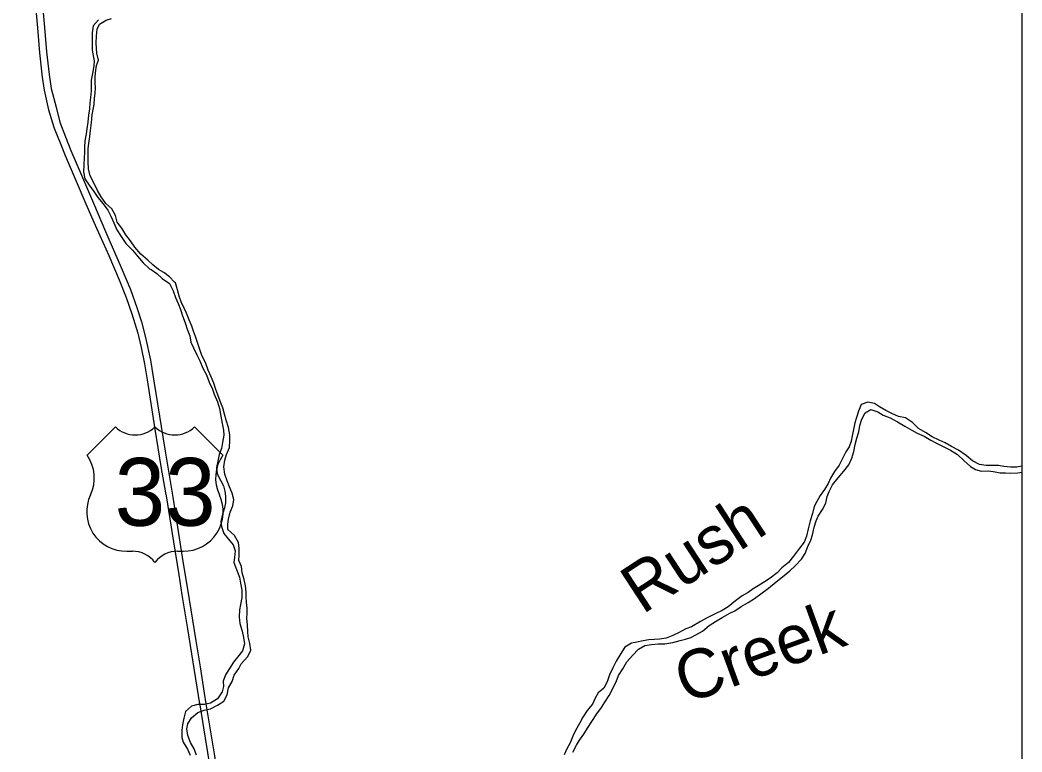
# Model space of a CAD drawing. Extents: x -51.9 to 34, y 0 to 23.3.
# Drawn here: x 9.235 to 12.658, y 13.737 to 16.239 of the extents above; entities that cross this region are included whole.
import ezdxf

# ---------------------------------------------------------------- set-up
doc = ezdxf.new("R2010")
doc.units = 0
for name, color, linetype in [('GM_X_Major_River', 7, 'Continuous'), ('GM_X_Major_River_Text', 7, 'Continuous'), ('GM_X_US_Route', 7, 'Continuous'), ('GM_X_US_Shield', 7, 'Continuous'), ('SH_Text', 7, 'Continuous')]:
    doc.layers.add(name, color=color, linetype=linetype)

msp = doc.modelspace()

# ---------------------------------------------------------------- linework, layer by layer
at = {"layer": 'GM_X_Major_River'}
for points in [[(9.5028, 16.2393), (9.4849, 16.2192), (9.4817, 16.1952), (9.4811, 16.1785), (9.4812, 16.1372), (9.4852, 16.1159), (9.4879, 16.0992), (9.4867, 16.0825), (9.4827, 16.0565), (9.4782, 16.0332), (9.4782, 16.0132), (9.4776, 15.9965), (9.4757, 15.9738), (9.4737, 15.9558), (9.4718, 15.9352), (9.4692, 15.9138), (9.4666, 15.8898), (9.4633, 15.8665), (9.4607, 15.8498), (9.4568, 15.8258), (9.4556, 15.8038), (9.4549, 15.7871), (9.4543, 15.7671), (9.4524, 15.7438), (9.4518, 15.7198), (9.4565, 15.6958), (9.4705, 15.6745), (9.4865, 15.6526), (9.5005, 15.6319), (9.5185, 15.6107), (9.5352, 15.5887), (9.5452, 15.5688), (9.5552, 15.5461), (9.5659, 15.5222), (9.58, 15.4989), (9.5966, 15.4756), (9.6186, 15.4523), (9.6359, 15.4317), (9.6559, 15.4091), (9.6772, 15.3885), (9.6832, 15.3866)], [(9.7657, 15.3402), (9.7624, 15.3428), (9.7457, 15.3614), (9.7258, 15.376), (9.7085, 15.3867), (9.6885, 15.4026), (9.6712, 15.4185), (9.6479, 15.4391), (9.6272, 15.4624), (9.6119, 15.4837), (9.5959, 15.5049), (9.5825, 15.5276), (9.5665, 15.5482), (9.5605, 15.5708), (9.5485, 15.5934), (9.5285, 15.612), (9.5118, 15.634), (9.4991, 15.6566), (9.4878, 15.6806), (9.4744, 15.7058), (9.4684, 15.7305), (9.4676, 15.7545), (9.4676, 15.7778), (9.4682, 15.7992), (9.4695, 15.8165), (9.4734, 15.8405), (9.476, 15.8612), (9.4786, 15.8885), (9.4811, 15.9152), (9.4844, 15.9332), (9.4877, 15.9499), (9.4896, 15.9719), (9.4916, 15.9892), (9.4922, 16.0066), (9.4915, 16.0252), (9.4914, 16.0459), (9.494, 16.0672), (9.4966, 16.0839), (9.5025, 16.1019), (9.4972, 16.1252), (9.4958, 16.1426), (9.4951, 16.1599), (9.4957, 16.1846), (9.4989, 16.2072), (9.5069, 16.2246), (9.5287, 16.2387), (9.5473, 16.2441)], [(9.6832, 15.3866), (9.7019, 15.3726), (9.7205, 15.3554), (9.7451, 15.3381), (9.7585, 15.3135), (9.7665, 15.2909), (9.7746, 15.2696), (9.7826, 15.2496), (9.79, 15.2276), (9.7993, 15.2036), (9.8054, 15.1823), (9.8154, 15.159), (9.8188, 15.1384), (9.8275, 15.1184), (9.8395, 15.0951), (9.8495, 15.0738), (9.8595, 15.0492), (9.8722, 15.0266), (9.8816, 15.0013), (9.8923, 14.9773), (9.8983, 14.9607), (9.909, 14.934), (9.9164, 14.9107), (9.9211, 14.8854), (9.9258, 14.8594), (9.9299, 14.8368), (9.9312, 14.8201), (9.9267, 14.7954), (9.9227, 14.7747), (9.9155, 14.7541), (9.9109, 14.7314), (9.9063, 14.71), (9.9084, 14.688), (9.9211, 14.6641), (9.9297, 14.6468), (9.9344, 14.6288), (9.9365, 14.6121), (9.9372, 14.5888)], [(9.9532, 14.5569), (9.9618, 14.5782), (9.9651, 14.6002), (9.9597, 14.6222), (9.951, 14.6435), (9.943, 14.6635), (9.9349, 14.6868), (9.9316, 14.7114), (9.9341, 14.7348), (9.9401, 14.7541), (9.9506, 14.7782), (9.9519, 14.8002), (9.9512, 14.8215), (9.9471, 14.8462), (9.9397, 14.8708), (9.933, 14.8914), (9.9277, 14.9134), (9.919, 14.9367), (9.9109, 14.958), (9.9042, 14.976), (9.8969, 14.9973), (9.8882, 15.0193), (9.8782, 15.0426), (9.8681, 15.0679), (9.8561, 15.0925), (9.8481, 15.1165), (9.8407, 15.1364), (9.834, 15.1578), (9.828, 15.1751), (9.8213, 15.1924), (9.8132, 15.2144), (9.8032, 15.237), (9.7952, 15.2543), (9.7858, 15.2756), (9.7798, 15.2922), (9.7724, 15.3162), (9.7657, 15.3402)], [(12.6582, 14.7138), (12.6404, 14.7104), (12.6192, 14.7103), (12.5959, 14.7129), (12.578, 14.7168), (12.5607, 14.7168), (12.5361, 14.7167), (12.5129, 14.7193), (12.4896, 14.7319), (12.4676, 14.7511), (12.4417, 14.7684), (12.4177, 14.781), (12.3964, 14.7942), (12.3751, 14.8028), (12.3519, 14.8141), (12.3286, 14.8293), (12.3053, 14.8433), (12.2846, 14.8632), (12.26, 14.8798), (12.2361, 14.8844), (12.2141, 14.8943), (12.1928, 14.9049), (12.1715, 14.9168), (12.1542, 14.9281), (12.1316, 14.9327), (12.1091, 14.9246), (12.0992, 14.9019), (12.0926, 14.8799), (12.0873, 14.8626), (12.0828, 14.8399), (12.0782, 14.8179), (12.0742, 14.7992), (12.0676, 14.7798), (12.0564, 14.7631), (12.0445, 14.7398), (12.0339, 14.7177), (12.0174, 14.6963), (12.0042, 14.673), (11.9956, 14.6549), (11.983, 14.6349), (11.9691, 14.6142), (11.9579, 14.5935), (11.9486, 14.5768), (11.9421, 14.5521), (11.9348, 14.5274), (11.9283, 14.5001), (11.9223, 14.4747), (11.9138, 14.454), (11.8946, 14.4293), (11.878, 14.4066), (11.8602, 14.3845), (11.8376, 14.3671), (11.8217, 14.349), (11.7979, 14.331), (11.7753, 14.3169), (11.7568, 14.3055)], [(11.8656, 14.3559), (11.8828, 14.3739), (11.9046, 14.396), (11.9179, 14.416), (11.9271, 14.4394), (11.9363, 14.4614), (11.9429, 14.4794), (11.9488, 14.5055), (11.9554, 14.5268), (11.962, 14.5435), (11.9766, 14.5655), (11.9885, 14.5882), (11.993, 14.6109), (11.999, 14.6276), (12.0109, 14.6503), (12.0301, 14.6744), (12.0499, 14.6971), (12.0665, 14.7192), (12.077, 14.7412), (12.0843, 14.7645), (12.0889, 14.7879), (12.0941, 14.8099), (12.1007, 14.8319), (12.104, 14.8533), (12.1106, 14.8746), (12.1225, 14.896), (12.1417, 14.9074), (12.1656, 14.9001), (12.1842, 14.8882), (12.2075, 14.8796), (12.2328, 14.8657), (12.2581, 14.8511), (12.2814, 14.8372), (12.3, 14.8273), (12.3239, 14.8167), (12.3466, 14.8027), (12.3639, 14.7935), (12.3885, 14.7809), (12.4138, 14.769), (12.4384, 14.7537), (12.4597, 14.7338), (12.4823, 14.7125), (12.4996, 14.7032), (12.5196, 14.6973), (12.5448, 14.6981), (12.5667, 14.6948), (12.584, 14.6909), (12.602, 14.6909), (12.6192, 14.6903), (12.6445, 14.6917), (12.6582, 14.6933)], [(9.9372, 14.5888), (9.9339, 14.5715), (9.9267, 14.5501), (9.9208, 14.5254), (9.9228, 14.5081), (9.9309, 14.4835), (9.9462, 14.4662), (9.9628, 14.4456), (9.9702, 14.4249), (9.9676, 14.4016), (9.965, 14.3849), (9.9744, 14.3609), (9.9844, 14.335), (9.9885, 14.3143), (9.9932, 14.2903), (9.9932, 14.265), (9.9887, 14.241), (9.9847, 14.223), (9.9835, 14.1997), (9.9862, 14.1763), (9.9936, 14.1504), (9.9983, 14.1284), (10.0017, 14.1071), (9.9951, 14.083), (9.9779, 14.061), (9.9646, 14.0443), (9.9507, 14.0222), (9.9369, 14.0008), (9.9289, 13.9795), (9.9297, 13.9608), (9.9251, 13.9428), (9.9092, 13.9188), (9.886, 13.9047), (9.8654, 13.8999), (9.8421, 13.8992), (9.8209, 13.8938), (9.7997, 13.8751), (9.7944, 13.8524), (9.7899, 13.8304), (9.7873, 13.8117), (9.7873, 13.787), (9.792, 13.7704), (9.8067, 13.7471), (9.8167, 13.7265)], [(9.838, 13.7265), (9.8299, 13.7478), (9.8173, 13.7698), (9.8086, 13.7938), (9.8052, 13.8164), (9.8078, 13.8331), (9.821, 13.8538), (9.8429, 13.8719), (9.8635, 13.8799), (9.886, 13.8847), (9.9092, 13.8974), (9.9311, 13.9108), (9.943, 13.9322), (9.9476, 13.9562), (9.9602, 13.9783), (9.9667, 14.0003), (9.982, 14.0223), (9.9906, 14.039), (10.0131, 14.0631), (10.0236, 14.0851), (10.0203, 14.1078), (10.0142, 14.1304), (10.0128, 14.1491), (10.0121, 14.1704), (10.01, 14.1944), (10.0107, 14.2111), (10.0106, 14.2284), (10.0086, 14.2497), (10.0072, 14.2671), (10.0071, 14.2837), (10.0051, 14.3051), (10.0004, 14.3264), (9.9937, 14.349), (9.9916, 14.371), (9.9829, 14.3916), (9.9835, 14.4096), (9.9841, 14.4323), (9.9814, 14.453), (9.9674, 14.4776), (9.9454, 14.4975), (9.9447, 14.5155), (9.9467, 14.5335), (9.9532, 14.5569)], [(11.1233, 13.7368), (11.1365, 13.7602), (11.1464, 13.7775), (11.161, 13.7982), (11.1742, 13.8183), (11.1881, 13.8417), (11.206, 13.8677), (11.2219, 13.8898), (11.2331, 13.9071), (11.2476, 13.9305), (11.2714, 13.9773), (11.28, 13.9986), (11.2946, 14.022), (11.3078, 14.0454), (11.3276, 14.0674), (11.3482, 14.0888), (11.3694, 14.1009), (11.392, 14.1043), (11.4152, 14.1064), (11.4378, 14.1071), (11.4657, 14.1112), (11.4909, 14.1186), (11.5088, 14.1227), (11.5267, 14.1288), (11.544, 14.1381), (11.5672, 14.1502), (11.5897, 14.1696), (11.6116, 14.183), (11.6335, 14.1964), (11.66, 14.2112), (11.6773, 14.2192), (11.6992, 14.234), (11.7224, 14.2481), (11.7443, 14.2621), (11.7655, 14.2782), (11.792, 14.297), (11.8185, 14.3184), (11.8404, 14.3364), (11.8656, 14.3559)], [(11.7568, 14.3055), (11.7395, 14.2948), (11.7223, 14.2821), (11.7017, 14.2713), (11.6798, 14.2533), (11.6547, 14.2338), (11.6341, 14.2211), (11.6096, 14.2097), (11.5804, 14.1943), (11.5598, 14.1829), (11.5286, 14.1654), (11.5101, 14.158), (11.4849, 14.144), (11.465, 14.1352), (11.4431, 14.1265), (11.4198, 14.1224), (11.4012, 14.1217), (11.3833, 14.121), (11.364, 14.1176), (11.3428, 14.1128), (11.3242, 14.1088), (11.3017, 14.0954), (11.2871, 14.074), (11.2712, 14.0473), (11.2607, 14.0246), (11.2494, 14.0005), (11.2409, 13.9765), (11.2296, 13.9551), (11.2098, 13.9391), (11.2005, 13.921), (11.1913, 13.9003), (11.1721, 13.8789), (11.1582, 13.8562), (11.1469, 13.8342), (11.1331, 13.8102), (11.1231, 13.7915), (11.1146, 13.7688), (11.102, 13.7454), (11.0941, 13.728)]]:
    msp.add_lwpolyline(points, dxfattribs=at)
at = {"layer": 'GM_X_US_Route'}
for points in [[(9.282, 16.3528), (9.2946, 16.2117), (9.3015, 16.1264), (9.3105, 16.0434), (9.3172, 15.9992), (9.3319, 15.9324), (9.3507, 15.8723), (9.3519, 15.8691)], [(9.3056, 16.352), (9.3183, 16.2132), (9.3252, 16.1299), (9.3345, 16.0521), (9.3417, 16.0053), (9.3588, 15.9411), (9.3709, 15.8899), (9.3897, 15.8399), (9.4085, 15.7927), (9.445, 15.7089), (9.486, 15.6129), (9.5274, 15.516), (9.5806, 15.3931), (9.6124, 15.3174), (9.6344, 15.2569), (9.6497, 15.2075), (9.6638, 15.1543), (9.6806, 15.0762), (9.6936, 14.9981), (9.7176, 14.8495), (9.7309, 14.7654), (9.7564, 14.6078), (9.7891, 14.4036), (9.8131, 14.2579), (9.8356, 14.1174), (9.8501, 14.028), (9.8642, 13.9378), (9.8699, 13.9021)], [(9.3519, 15.8691), (9.3738, 15.813), (9.3892, 15.7757), (9.4198, 15.704), (9.4597, 15.6106), (9.4874, 15.5481)], [(9.4874, 15.5481), (9.5378, 15.4345), (9.5739, 15.3509), (9.5976, 15.2905), (9.6173, 15.235), (9.6372, 15.169), (9.6491, 15.1196), (9.6598, 15.0635), (9.6693, 15.0088), (9.6951, 14.8411), (9.7162, 14.7128), (9.7323, 14.6228)], [(9.7323, 14.6228), (9.7341, 14.6124), (9.7593, 14.456), (9.7778, 14.3432), (9.7882, 14.2744), (9.807, 14.1582), (9.8298, 14.0153), (9.8486, 13.9014), (9.8492, 13.898)], [(9.8699, 13.9021), (9.8732, 13.8817), (9.8992, 13.7236), (9.9313, 13.5238), (9.9495, 13.4084), (9.9787, 13.2288), (9.9952, 13.1247), (10.012, 13.0195), (10.0397, 12.8486), (10.0675, 12.6751), (10.0912, 12.5317), (10.11, 12.4154), (10.124, 12.3317)], [(9.8492, 13.898), (9.8677, 13.7849), (9.8989, 13.5882), (9.9281, 13.4092), (9.9547, 13.2412), (9.9779, 13.0999), (9.992, 13.0102), (10.0163, 12.857), (10.0452, 12.6835), (10.0713, 12.5189), (10.1024, 12.328)]]:
    msp.add_lwpolyline(points, dxfattribs=at)
at = {"layer": 'GM_X_US_Shield'}
for p, q in [((9.5607, 14.8483), (9.4641, 14.7518)), ((9.9276, 14.7518), (9.831, 14.8483)), ((9.5993, 14.4235), (9.6186, 14.4235)), ((9.7731, 14.4235), (9.7924, 14.4235))]:
    msp.add_line(p, q, dxfattribs=at)
for centre, radius, start, end in [((9.6283, 14.9173), 0.0966, 225.573, 314.427), ((9.7634, 14.9173), 0.0966, 225.573, 314.427), ((9.3534, 14.6742), 0.1352, 334.5471, 35.0009), ((10.0383, 14.6742), 0.1352, 144.9991, 205.4529), ((9.5978, 14.5587), 0.1352, 154.8319, 270.6383), ((9.7939, 14.5587), 0.1352, 269.3617, 25.1681), ((9.6186, 14.3269), 0.0966, 36.8699, 90), ((9.7731, 14.3269), 0.0966, 90, 143.1301)]:
    msp.add_arc(centre, radius, start, end, dxfattribs=at)
at = {"layer": 'SH_Text'}
msp.add_lwpolyline([(2.2024, 20.8014), (12.6582, 20.8014), (12.6582, 11.236), (2.2024, 11.236)], close=True, dxfattribs=at)

# ---------------------------------------------------------------- texts
at = {"layer": 'GM_X_Major_River_Text'}
for s, rotation, p in [('Rush', 33.1478, (11.3612, 14.2055)), ('Creek', 20.0685, (11.5101, 13.9003))]:
    msp.add_text(s, height=0.16645, rotation=rotation, dxfattribs=at).set_placement(p)
at = {"layer": 'GM_X_US_Shield'}
msp.add_text('33', height=0.23174, dxfattribs=at).set_placement((9.5583, 14.5104))

doc.saveas('drawing.dxf')
